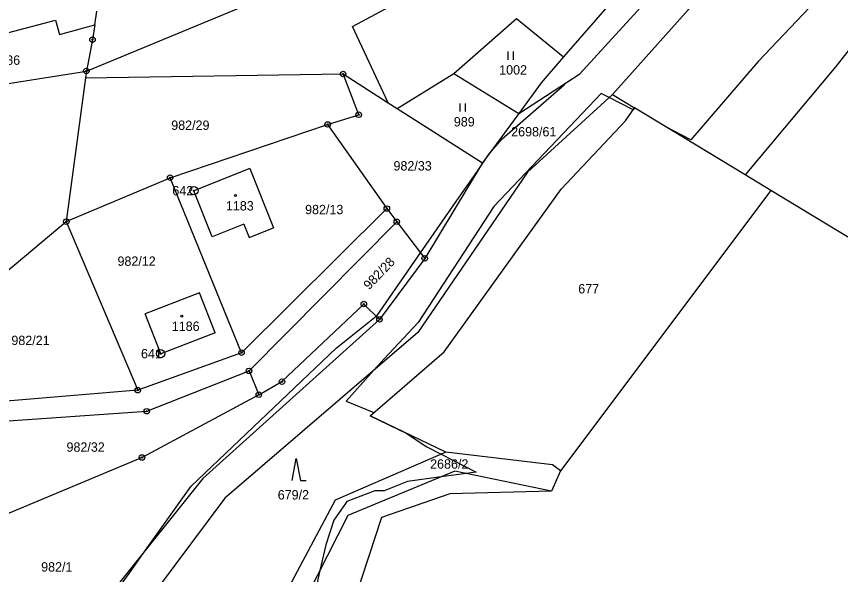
# Model space of a CAD drawing. Extents: x -439246 to -433691, y -1130252 to -1121148.
# Drawn here: x -437973 to -437823.2, y -1124324.9 to -1124223.5 of the extents above; entities that cross this region are included whole.
import ezdxf

# ---------------------------------------------------------------- set-up
doc = ezdxf.new("R2010")
doc.units = 0
for name, color, linetype in [('Vrstva 1', 7, 'Continuous'), ('Vrstva 16', 7, 'Continuous'), ('Vrstva 17', 7, 'Continuous'), ('Vrstva 18', 7, 'Continuous'), ('Vrstva 19', 7, 'Continuous'), ('Vrstva 24', 7, 'Continuous'), ('Vrstva 25', 7, 'Continuous'), ('Vrstva 3', 7, 'Continuous'), ('Vrstva 37', 7, 'Continuous'), ('Vrstva 52', 7, 'Continuous'), ('Vrstva 6', 7, 'Continuous')]:
    doc.layers.add(name, color=color, linetype=linetype)

msp = doc.modelspace()

# ---------------------------------------------------------------- linework, layer by layer
at = {"layer": 'Vrstva 1'}
for points in [[(-437864.67, -1124237.67), (-437830.95, -1124199.98)], [(-437911.95, -1124225.34), (-437885.93, -1124211.33)], [(-437856.56, -1124211.29), (-437873.55, -1124230.87)], [(-437870.61, -1124233.92), (-437852.34, -1124213.96)], [(-437960.31, -1124233.42), (-437916.03, -1124215.11)], [(-437811.23, -1124216.33), (-437824.07, -1124232.59)], [(-437958.79, -1124225.04), (-437958.42, -1124222.54)], [(-437990.99, -1124230.76), (-437965.91, -1124224.17)], [(-437965.91, -1124224.17), (-437965.22, -1124226.76)], [(-437965.22, -1124226.76), (-437958.79, -1124225.04)], [(-437958.79, -1124225.04), (-437959.19, -1124227.72)], [(-437893.51, -1124233.84), (-437882.1, -1124223.88)], [(-437882.1, -1124223.88), (-437873.55, -1124230.87)], [(-437905.43, -1124239.18), (-437911.95, -1124225.34)], [(-437959.19, -1124227.72), (-437960.31, -1124233.42)], [(-437873.55, -1124230.87), (-437877.61, -1124235.55)], [(-437824.07, -1124232.59), (-437840.56, -1124252.27)], [(-437991.49, -1124238.36), (-437960.31, -1124233.42)], [(-437960.31, -1124233.42), (-437960.47, -1124234.63)], [(-437960.47, -1124234.63), (-437913.63, -1124233.96)], [(-437913.63, -1124233.96), (-437905.43, -1124239.18)], [(-437910.79, -1124241.36), (-437913.63, -1124233.96)], [(-437903.79, -1124240.23), (-437893.51, -1124233.84)], [(-437893.51, -1124233.84), (-437881.7, -1124241.11)], [(-437881.7, -1124241.11), (-437870.61, -1124233.92)], [(-437960.47, -1124234.63), (-437963.96, -1124260.77)], [(-437877.61, -1124235.55), (-437881.7, -1124241.11)], [(-437864.67, -1124237.67), (-437880.13, -1124251.8)], [(-437905.43, -1124239.18), (-437903.79, -1124240.23)], [(-437903.79, -1124240.23), (-437888.29, -1124250.07)], [(-437862.28, -1124242.46), (-437860.64, -1124240.11)], [(-437840.56, -1124252.27), (-437860.64, -1124240.11)], [(-437916.45, -1124243.12), (-437910.79, -1124241.36)], [(-437881.7, -1124241.11), (-437888.29, -1124250.07)], [(-437945.08, -1124252.79), (-437916.45, -1124243.12)], [(-437916.45, -1124243.12), (-437905.68, -1124258.4)], [(-437873.97, -1124254.9), (-437862.28, -1124242.46)], [(-437888.29, -1124250.07), (-437898.79, -1124267.44)], [(-437930.59, -1124251.11), (-437940.75, -1124255.18)], [(-437930.59, -1124251.11), (-437926.29, -1124261.87)], [(-437880.13, -1124251.8), (-437900.05, -1124280.91)], [(-437835.84, -1124255.13), (-437840.56, -1124252.27)], [(-437963.96, -1124260.77), (-437945.08, -1124252.79)], [(-437932.09, -1124284.58), (-437945.08, -1124252.79)], [(-437937.42, -1124263.51), (-437940.75, -1124255.18)], [(-437895.28, -1124284.42), (-437873.97, -1124254.9)], [(-437835.84, -1124255.13), (-437874.12, -1124306.05)], [(-437810.12, -1124270.69), (-437835.84, -1124255.13)], [(-437905.68, -1124258.4), (-437932.09, -1124284.58)], [(-437905.68, -1124258.4), (-437903.87, -1124260.8)], [(-437996.6, -1124288.08), (-437963.96, -1124260.77)], [(-437963.96, -1124260.77), (-437950.96, -1124291.38)], [(-437931.68, -1124261.21), (-437937.42, -1124263.51)], [(-437931.68, -1124261.21), (-437930.71, -1124263.64)], [(-437930.73, -1124287.88), (-437903.87, -1124260.8)], [(-437903.87, -1124260.8), (-437898.79, -1124267.44)], [(-437930.71, -1124263.64), (-437926.29, -1124261.87)], [(-437898.79, -1124267.44), (-437907.02, -1124278.54)], [(-437939.71, -1124273.7), (-437949.61, -1124277.51)], [(-437936.9, -1124281), (-437939.71, -1124273.7)], [(-437924.75, -1124289.83), (-437909.86, -1124275.74)], [(-437909.86, -1124275.74), (-437907.02, -1124278.54)], [(-437946.77, -1124284.8), (-437949.61, -1124277.51)], [(-437907.02, -1124278.54), (-437939.12, -1124307.45)], [(-437936.9, -1124281), (-437946.77, -1124284.8)], [(-437900.05, -1124280.91), (-437935.16, -1124311)], [(-437932.09, -1124284.58), (-437950.96, -1124291.38)], [(-437908.73, -1124296.02), (-437895.28, -1124284.42)], [(-437949.33, -1124295.21), (-437930.73, -1124287.88)], [(-437930.73, -1124287.88), (-437928.96, -1124292.21)], [(-437928.96, -1124292.21), (-437924.75, -1124289.83)], [(-437950.96, -1124291.38), (-437997.33, -1124295.28)], [(-437928.96, -1124292.21), (-437950.19, -1124303.61)], [(-437976.29, -1124297.1), (-437949.33, -1124295.21)], [(-437894.96, -1124302.62), (-437908.73, -1124296.02)], [(-437894.96, -1124302.62), (-437915.09, -1124311.34)], [(-437875.57, -1124304.96), (-437894.96, -1124302.62)], [(-437950.19, -1124303.61), (-437975.08, -1124314.02)], [(-437893.31, -1124306.11), (-437912.75, -1124314.16)], [(-437875.77, -1124309.73), (-437893.31, -1124306.11)], [(-437874.12, -1124306.05), (-437875.77, -1124309.73)], [(-437874.12, -1124306.05), (-437875.57, -1124304.96)], [(-437939.12, -1124307.45), (-437970.53, -1124346.61)], [(-437894.22, -1124310.19), (-437906.65, -1124314.53)], [(-437875.77, -1124309.73), (-437894.22, -1124310.19)], [(-437935.16, -1124311), (-437962.59, -1124347.76)], [(-437915.09, -1124311.34), (-437923.98, -1124328.06)], [(-437912.75, -1124314.16), (-437920.22, -1124328.8)], [(-437906.65, -1124314.53), (-437912.6, -1124332.6)]]:
    msp.add_lwpolyline(points, dxfattribs=at)
at = {"layer": 'Vrstva 24'}
for centre, radius in [((-437959.19, -1124227.72), 0.5), ((-437959.19, -1124227.72), 0.1), ((-437960.31, -1124233.42), 0.5), ((-437960.31, -1124233.42), 0.1), ((-437913.63, -1124233.96), 0.5), ((-437913.63, -1124233.96), 0.1), ((-437910.79, -1124241.36), 0.5), ((-437910.79, -1124241.36), 0.1), ((-437916.45, -1124243.12), 0.5), ((-437916.45, -1124243.12), 0.1), ((-437945.08, -1124252.79), 0.5), ((-437945.08, -1124252.79), 0.1), ((-437940.76, -1124255.16), 0.75), ((-437940.76, -1124255.16), 0.1), ((-437905.68, -1124258.4), 0.5), ((-437905.68, -1124258.4), 0.1), ((-437963.96, -1124260.77), 0.5), ((-437963.96, -1124260.77), 0.1), ((-437903.87, -1124260.8), 0.5), ((-437903.87, -1124260.8), 0.1), ((-437898.79, -1124267.44), 0.5), ((-437898.79, -1124267.44), 0.1), ((-437909.86, -1124275.74), 0.5), ((-437909.86, -1124275.74), 0.1), ((-437907.02, -1124278.54), 0.5), ((-437907.02, -1124278.54), 0.1), ((-437946.81, -1124284.75), 0.75), ((-437946.81, -1124284.75), 0.1), ((-437932.09, -1124284.58), 0.5), ((-437932.09, -1124284.58), 0.1), ((-437930.73, -1124287.88), 0.5), ((-437930.73, -1124287.88), 0.1), ((-437924.75, -1124289.83), 0.5), ((-437924.75, -1124289.83), 0.1), ((-437950.96, -1124291.38), 0.5), ((-437950.96, -1124291.38), 0.1), ((-437928.96, -1124292.21), 0.5), ((-437928.96, -1124292.21), 0.1), ((-437949.33, -1124295.21), 0.5), ((-437949.33, -1124295.21), 0.1), ((-437950.19, -1124303.61), 0.5), ((-437950.19, -1124303.61), 0.1)]:
    msp.add_circle(centre, radius, dxfattribs=at)
at = {"layer": 'Vrstva 25'}
for p, q in [((-437883.63, -1124231.36), (-437883.63, -1124229.86)), ((-437882.63, -1124231.36), (-437882.63, -1124229.86)), ((-437892.35, -1124240.79), (-437892.35, -1124239.29)), ((-437891.35, -1124240.79), (-437891.35, -1124239.29))]:
    msp.add_line(p, q, dxfattribs=at)
msp.add_lwpolyline([(-437922.87, -1124307.79), (-437922.17, -1124303.79), (-437921.37, -1124307.79), (-437920.37, -1124307.79)], dxfattribs=at)
for centre in [(-437933.18, -1124256.05), (-437942.97, -1124277.92)]:
    msp.add_circle(centre, 0.175, dxfattribs=at)
at = {"layer": 'Vrstva 3'}
for points in [[(-437930.59, -1124251.11), (-437940.75, -1124255.18)], [(-437930.59, -1124251.11), (-437926.29, -1124261.87)], [(-437937.42, -1124263.51), (-437940.75, -1124255.18)], [(-437931.68, -1124261.21), (-437937.42, -1124263.51)], [(-437931.68, -1124261.21), (-437930.71, -1124263.64)], [(-437930.71, -1124263.64), (-437926.29, -1124261.87)], [(-437939.71, -1124273.7), (-437949.61, -1124277.51)], [(-437936.9, -1124281), (-437939.71, -1124273.7)], [(-437946.77, -1124284.8), (-437949.61, -1124277.51)], [(-437936.9, -1124281), (-437946.77, -1124284.8)]]:
    msp.add_lwpolyline(points, dxfattribs=at)
at = {"layer": 'Vrstva 37'}
for centre in [(-437933.18, -1124256.05), (-437942.97, -1124277.92)]:
    msp.add_circle(centre, 0.175, dxfattribs=at)
at = {"layer": 'Vrstva 52'}
for points in [[(-437955.67, -1124329.01), (-437952.55, -1124324.65), (-437949.55, -1124320.45), (-437941.23, -1124308.82), (-437914.88, -1124283.75), (-437912.18, -1124281.59), (-437907.62, -1124277.95), (-437907.44, -1124277.8), (-437899.55, -1124266.45), (-437892.53, -1124256.36), (-437889.21, -1124251.61), (-437887.05, -1124248.48), (-437884.71, -1124245.72), (-437873.45, -1124235.95), (-437873.01, -1124235.48), (-437870.61, -1124233.92), (-437852.34, -1124213.96), (-437840.45, -1124201.7), (-437835.42, -1124196.85), (-437816.83, -1124183.73)], [(-437826.49, -1124219.37), (-437838.18, -1124231.7), (-437850.39, -1124245.91), (-437854.94, -1124243.56), (-437860.64, -1124240.11), (-437860.9, -1124240.49), (-437865.28, -1124238.23), (-437866.72, -1124237.49), (-437886.2, -1124258.04), (-437900.01, -1124279.08), (-437906.17, -1124285.67), (-437908.03, -1124287.75), (-437910.05, -1124290.01), (-437913.06, -1124293.37), (-437908.05, -1124295.44), (-437908.73, -1124296.02), (-437902.03, -1124299.23), (-437898.52, -1124301.6), (-437895.82, -1124302.99), (-437889.44, -1124306.29), (-437891.25, -1124306.53), (-437895.83, -1124307.15), (-437901.92, -1124307.97), (-437906.17, -1124309.67), (-437907.87, -1124309.67), (-437912.97, -1124311.59), (-437913.22, -1124311.96), (-437915.3, -1124314.99), (-437916.79, -1124319.45), (-437917.85, -1124324.16), (-437918.94, -1124329.03)]]:
    msp.add_lwpolyline(points, dxfattribs=at)
at = {"layer": 'Vrstva 6'}
msp.add_lwpolyline([(-437864.67, -1124237.67), (-437860.64, -1124240.11)], dxfattribs=at)

# ---------------------------------------------------------------- texts
at = {"layer": 'Vrstva 16'}
msp.add_text('2698/61', height=1.7, dxfattribs=at).set_placement((-437883.07, -1124245.29))
at = {"layer": 'Vrstva 17'}
for s, p in [('642', (-437944.68, -1124256.01)), ('641', (-437950.37, -1124285.6))]:
    msp.add_text(s, height=1.7, dxfattribs=at).set_placement(p)
at = {"layer": 'Vrstva 18'}
for s, p in [('986', (-437976.14, -1124232.29)), ('1002', (-437885.25, -1124234.06)), ('989', (-437893.5, -1124243.49)), ('982/29', (-437944.88, -1124244.11)), ('982/33', (-437904.47, -1124251.49)), ('982/13', (-437920.54, -1124259.43)), ('982/12', (-437954.65, -1124268.8)), ('677', (-437870.88, -1124273.82)), ('982/21', (-437973.94, -1124283.19)), ('982/32', (-437963.92, -1124302.57)), ('2686/2', (-437897.81, -1124305.64)), ('679/2', (-437925.52, -1124311.24)), ('982/1', (-437968.53, -1124324.33))]:
    msp.add_text(s, height=1.7, dxfattribs=at).set_placement(p)
msp.add_text('982/28', height=1.7, rotation=46.2305, dxfattribs=at).set_placement((-437908.89, -1124273.25))
at = {"layer": 'Vrstva 19'}
for s, p in [('1183', (-437934.94, -1124258.75)), ('1186', (-437944.78, -1124280.62))]:
    msp.add_text(s, height=1.7, dxfattribs=at).set_placement(p)

doc.saveas('drawing.dxf')
